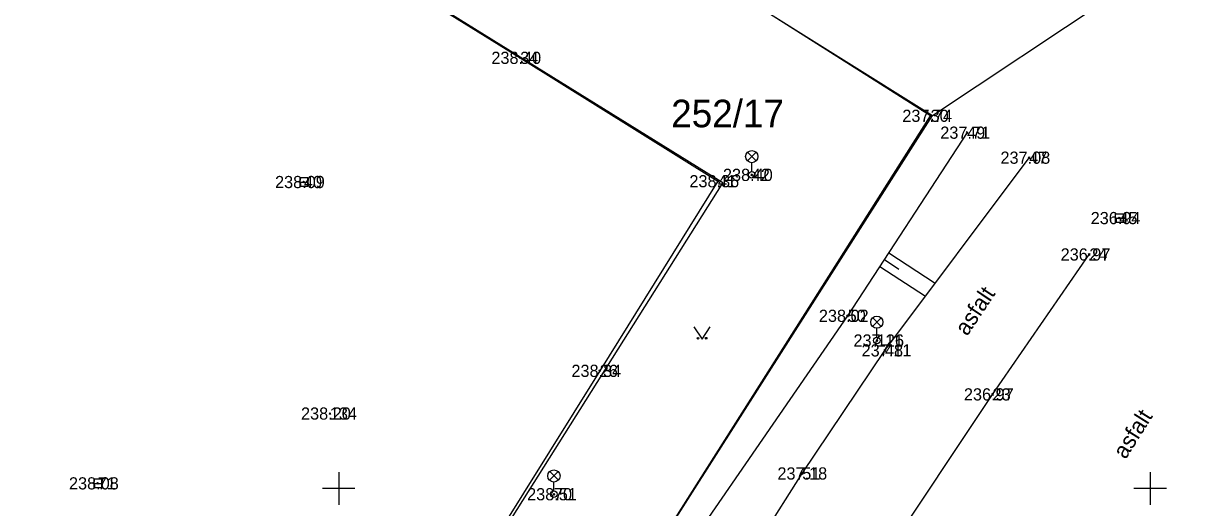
# Model space of a CAD drawing. Extents: x -645398 to -644998, y -1063322 to -1063031.
# Drawn here: x -645269.4 to -645197.8, y -1063151.2 to -1063121.3 of the extents above; entities that cross this region are included whole.
import ezdxf

# ---------------------------------------------------------------- set-up
doc = ezdxf.new("R2010")
doc.units = 0
for name, color, linetype in [('Bod', 7, 'Continuous'), ('Doplněk polohopisu', 7, 'Continuous'), ('Elektrický kabel', 7, 'Continuous'), ('Hranice KN pozemků', 7, 'Continuous'), ('Kanalizace', 7, 'Continuous'), ('Kultury', 7, 'Continuous'), ('Popisy povrchů', 7, 'Continuous'), ('Rozhraní ploch', 7, 'Continuous'), ('Souřadnicové křížky', 7, 'Continuous'), ('Výška', 7, 'Continuous'), ('Výškopis', 7, 'Continuous'), ('Čísla parcel', 7, 'Continuous'), ('Číslo bodu', 7, 'Continuous'), ('Šrafy', 7, 'Continuous')]:
    doc.layers.add(name, color=color, linetype=linetype)

msp = doc.modelspace()

# ---------------------------------------------------------------- linework, layer by layer
at = {"layer": 'Bod'}
for p, q in [((-645238.82, -1063123.47), (-645238.87, -1063123.42)), ((-645238.82, -1063123.47), (-645238.87, -1063123.52)), ((-645238.82, -1063123.47), (-645238.77, -1063123.42)), ((-645238.82, -1063123.47), (-645238.77, -1063123.52)), ((-645213.53, -1063127.04), (-645213.58, -1063126.99)), ((-645213.53, -1063127.04), (-645213.58, -1063127.09)), ((-645213.53, -1063127.04), (-645213.48, -1063126.99)), ((-645213.53, -1063127.04), (-645213.48, -1063127.09)), ((-645211.28, -1063128.08), (-645211.33, -1063128.03)), ((-645211.28, -1063128.08), (-645211.33, -1063128.13)), ((-645211.28, -1063128.08), (-645211.23, -1063128.03)), ((-645211.28, -1063128.08), (-645211.23, -1063128.13)), ((-645207.45, -1063129.62), (-645207.5, -1063129.57)), ((-645207.45, -1063129.62), (-645207.5, -1063129.67)), ((-645207.45, -1063129.62), (-645207.4, -1063129.57)), ((-645207.45, -1063129.62), (-645207.4, -1063129.67)), ((-645226.63, -1063131.07), (-645226.68, -1063131.02)), ((-645226.63, -1063131.07), (-645226.58, -1063131.02)), ((-645224.55, -1063130.68), (-645224.6, -1063130.63)), ((-645224.55, -1063130.68), (-645224.6, -1063130.73)), ((-645224.55, -1063130.68), (-645224.5, -1063130.63)), ((-645224.55, -1063130.68), (-645224.5, -1063130.73)), ((-645252.15, -1063131.12), (-645252.2, -1063131.07)), ((-645252.15, -1063131.12), (-645252.2, -1063131.17)), ((-645252.15, -1063131.12), (-645252.1, -1063131.07)), ((-645252.15, -1063131.12), (-645252.1, -1063131.17)), ((-645226.63, -1063131.07), (-645226.68, -1063131.12)), ((-645226.63, -1063131.07), (-645226.58, -1063131.12)), ((-645201.9, -1063133.34), (-645201.95, -1063133.29)), ((-645201.9, -1063133.34), (-645201.95, -1063133.39)), ((-645201.9, -1063133.34), (-645201.85, -1063133.29)), ((-645201.9, -1063133.34), (-645201.85, -1063133.39)), ((-645203.75, -1063135.58), (-645203.8, -1063135.53)), ((-645203.75, -1063135.58), (-645203.8, -1063135.63)), ((-645203.75, -1063135.58), (-645203.7, -1063135.53)), ((-645203.75, -1063135.58), (-645203.7, -1063135.63)), ((-645218.64, -1063139.36), (-645218.69, -1063139.31)), ((-645218.64, -1063139.36), (-645218.69, -1063139.41)), ((-645218.64, -1063139.36), (-645218.59, -1063139.31)), ((-645218.64, -1063139.36), (-645218.59, -1063139.41)), ((-645216.84, -1063140.88), (-645216.89, -1063140.83)), ((-645216.84, -1063140.88), (-645216.89, -1063140.93)), ((-645216.84, -1063140.88), (-645216.79, -1063140.83)), ((-645216.84, -1063140.88), (-645216.79, -1063140.93)), ((-645216.34, -1063141.49), (-645216.39, -1063141.44)), ((-645216.34, -1063141.49), (-645216.39, -1063141.54)), ((-645216.34, -1063141.49), (-645216.29, -1063141.44)), ((-645216.34, -1063141.49), (-645216.29, -1063141.54)), ((-645233.92, -1063142.75), (-645233.97, -1063142.7)), ((-645233.92, -1063142.75), (-645233.97, -1063142.8)), ((-645233.92, -1063142.75), (-645233.87, -1063142.7)), ((-645233.92, -1063142.75), (-645233.87, -1063142.8)), ((-645209.71, -1063144.2), (-645209.76, -1063144.15)), ((-645209.71, -1063144.2), (-645209.76, -1063144.25)), ((-645209.71, -1063144.2), (-645209.66, -1063144.15)), ((-645209.71, -1063144.2), (-645209.66, -1063144.25)), ((-645250.55, -1063145.38), (-645250.6, -1063145.33)), ((-645250.55, -1063145.38), (-645250.6, -1063145.43)), ((-645250.55, -1063145.38), (-645250.5, -1063145.33)), ((-645250.55, -1063145.38), (-645250.5, -1063145.43)), ((-645264.85, -1063149.68), (-645264.9, -1063149.63)), ((-645264.85, -1063149.68), (-645264.9, -1063149.73)), ((-645264.85, -1063149.68), (-645264.8, -1063149.63)), ((-645264.85, -1063149.68), (-645264.8, -1063149.73)), ((-645221.44, -1063149.07), (-645221.49, -1063149.02)), ((-645221.44, -1063149.07), (-645221.49, -1063149.12)), ((-645221.44, -1063149.07), (-645221.39, -1063149.02)), ((-645221.44, -1063149.07), (-645221.39, -1063149.12)), ((-645236.74, -1063150.35), (-645236.79, -1063150.3)), ((-645236.74, -1063150.35), (-645236.79, -1063150.4)), ((-645236.74, -1063150.35), (-645236.69, -1063150.3)), ((-645236.74, -1063150.35), (-645236.69, -1063150.4))]:
    msp.add_line(p, q, dxfattribs=at)
at = {"layer": 'Doplněk polohopisu'}
for points in [[(-645213.53, -1063127.04), (-645277.54, -1063086.52), (-645278.26, -1063087.53), (-645280.16, -1063086.35)], [(-645255.41, -1063177.74), (-645248.02, -1063181.43), (-645245.24, -1063177.12), (-645241.54, -1063171.3), (-645234.08, -1063159.42), (-645213.53, -1063127.04)]]:
    msp.add_lwpolyline(points, dxfattribs=at)
at = {"layer": 'Elektrický kabel'}
for p, q in [((-645224.814, -1063129.818), (-645224.286, -1063129.29)), ((-645224.278, -1063129.815), (-645224.806, -1063129.286)), ((-645224.55, -1063130.48), (-645224.55, -1063129.93)), ((-645217.104, -1063140.018), (-645216.576, -1063139.49)), ((-645216.568, -1063140.015), (-645217.096, -1063139.486)), ((-645216.84, -1063140.68), (-645216.84, -1063140.13)), ((-645237.004, -1063149.488), (-645236.476, -1063148.96)), ((-645236.468, -1063149.485), (-645236.996, -1063148.956)), ((-645236.74, -1063150.15), (-645236.74, -1063149.6))]:
    msp.add_line(p, q, dxfattribs=at)
for centre, radius in [((-645224.55, -1063129.555), 0.375), ((-645224.55, -1063130.68), 0.2), ((-645216.84, -1063139.755), 0.375), ((-645216.84, -1063140.88), 0.2), ((-645236.74, -1063149.225), 0.375), ((-645236.74, -1063150.35), 0.2)]:
    msp.add_circle(centre, radius, dxfattribs=at)
at = {"layer": 'Hranice KN pozemků'}
for p, q in [((-645290.82, -1063091.17), (-645226.33, -1063131.14)), ((-645268.32, -1063092.65), (-645213.42, -1063127.02)), ((-645213.42, -1063127.02), (-645186.47, -1063109.12)), ((-645248.4, -1063181.97), (-645213.42, -1063127.02)), ((-645226.33, -1063131.14), (-645255.73, -1063177.75))]:
    msp.add_line(p, q, dxfattribs=at)
at = {"layer": 'Kanalizace'}
for p, q in [((-645252.4, -1063131.12), (-645251.9, -1063131.12)), ((-645202.15, -1063133.34), (-645201.65, -1063133.34)), ((-645265.1, -1063149.68), (-645264.6, -1063149.68))]:
    msp.add_line(p, q, dxfattribs=at)
for points in [[(-645252.4, -1063131.37), (-645251.9, -1063131.37), (-645251.9, -1063130.87), (-645252.4, -1063130.87)], [(-645202.15, -1063133.59), (-645201.65, -1063133.59), (-645201.65, -1063133.09), (-645202.15, -1063133.09)], [(-645265.1, -1063149.93), (-645264.6, -1063149.93), (-645264.6, -1063149.43), (-645265.1, -1063149.43)]]:
    msp.add_lwpolyline(points, close=True, dxfattribs=at)
at = {"layer": 'Kultury'}
msp.add_lwpolyline([(-645228.109, -1063140.041), (-645227.609, -1063140.791), (-645227.109, -1063140.041)], dxfattribs=at)
for centre in [(-645227.859, -1063140.741), (-645227.359, -1063140.741)]:
    msp.add_circle(centre, 0.05, dxfattribs=at)
at = {"layer": 'Rozhraní ploch'}
for points in [[(-645324.89, -1063137.57), (-645306.17, -1063108.34), (-645294.16, -1063089.19), (-645266.49, -1063106.33), (-645238.82, -1063123.47), (-645226.63, -1063131.07), (-645233.92, -1063142.75), (-645244.93, -1063160.38), (-645255.94, -1063178.02)], [(-645339.9, -1063127.53), (-645339.17, -1063128.33), (-645324.89, -1063137.57), (-645316.1, -1063143.14), (-645308.22, -1063148.13), (-645296.87, -1063155.59), (-645287.5, -1063161.41), (-645276.29, -1063168.88), (-645253.42, -1063181.56), (-645248.71, -1063182.39), (-645245.43, -1063182.1), (-645242.79, -1063180.82), (-645239.91, -1063178), (-645237.55, -1063174.54), (-645228.78, -1063160.66), (-645221.44, -1063149.07), (-645216.34, -1063141.49), (-645207.45, -1063129.62)], [(-645209.494, -1063173.126), (-645212.11, -1063171.48), (-645214.6, -1063169.69), (-645216.04, -1063167.99), (-645218.25, -1063163.86), (-645218.42, -1063158.59), (-645217.51, -1063156.26), (-645216.44, -1063154.29), (-645209.71, -1063144.2), (-645203.75, -1063135.58)]]:
    msp.add_lwpolyline(points, dxfattribs=at)
at = {"layer": 'Souřadnicové křížky'}
for p, q in [((-645250, -1063149), (-645250, -1063151)), ((-645200, -1063149), (-645200, -1063151)), ((-645249, -1063150), (-645251, -1063150)), ((-645199, -1063150), (-645201, -1063150))]:
    msp.add_line(p, q, dxfattribs=at)
at = {"layer": 'Výškopis'}
msp.add_lwpolyline([(-645211.28, -1063128.08), (-645218.64, -1063139.36), (-645233.09, -1063160.3), (-645240.7, -1063172.18), (-645243.51, -1063170.68), (-645245.27, -1063171.5), (-645250.05, -1063178.5), (-645255.94, -1063178.02)], dxfattribs=at)
at = {"layer": 'Šrafy'}
for p, q in [((-645216.379, -1063135.895), (-645215.481, -1063136.481)), ((-645216.106, -1063135.476), (-645213.238, -1063137.348)), ((-645216.653, -1063136.314), (-645213.839, -1063138.15))]:
    msp.add_line(p, q, dxfattribs=at)

# ---------------------------------------------------------------- texts
at = {"layer": 'Popisy povrchů'}
for rotation, p in [(56.29683, (-645211.279, -1063140.651)), (57.81013, (-645201.516, -1063148.245))]:
    msp.add_text('asfalt', height=1, rotation=rotation, dxfattribs=at).set_placement(p)
at = {"layer": 'Výška'}
for s, p in [('238.40', (-645240.595, -1063123.845)), ('237.74', (-645215.272, -1063127.415)), ('237.71', (-645212.933, -1063128.455)), ('237.08', (-645209.224, -1063129.995)), ('238.40', (-645226.325, -1063131.055)), ('238.09', (-645253.927, -1063131.495)), ('238.36', (-645228.393, -1063131.445)), ('236.94', (-645203.666, -1063133.715)), ('236.97', (-645205.516, -1063135.955)), ('238.02', (-645220.414, -1063139.735)), ('237.11', (-645218.281, -1063141.255)), ('237.11', (-645217.781, -1063141.865)), ('238.34', (-645235.662, -1063143.125)), ('236.97', (-645211.476, -1063144.575)), ('238.20', (-645252.325, -1063145.755)), ('237.18', (-645222.969, -1063149.445)), ('238.08', (-645266.624, -1063150.055)), ('238.51', (-645238.393, -1063150.725))]:
    msp.add_text(s, height=0.75, dxfattribs=at).set_placement(p)
at = {"layer": 'Čísla parcel'}
msp.add_text('252/17', height=1.7, dxfattribs=at).set_placement((-645229.515, -1063127.75))
at = {"layer": 'Číslo bodu'}
for s, p in [('34', (-645238.82, -1063123.845)), ('30', (-645213.53, -1063127.415)), ('49', (-645211.28, -1063128.455)), ('47', (-645207.45, -1063129.995)), ('42', (-645224.55, -1063131.055)), ('40', (-645252.15, -1063131.495)), ('41', (-645226.63, -1063131.445)), ('45', (-645201.9, -1063133.715)), ('24', (-645203.75, -1063135.955)), ('50', (-645218.64, -1063139.735)), ('126', (-645216.84, -1063141.255)), ('48', (-645216.34, -1063141.865)), ('26', (-645233.92, -1063143.125)), ('23', (-645209.71, -1063144.575)), ('134', (-645250.55, -1063145.755)), ('51', (-645221.44, -1063149.445)), ('71', (-645264.85, -1063150.055)), ('70', (-645236.74, -1063150.725))]:
    msp.add_text(s, height=0.75, dxfattribs=at).set_placement(p)

doc.saveas('drawing.dxf')
